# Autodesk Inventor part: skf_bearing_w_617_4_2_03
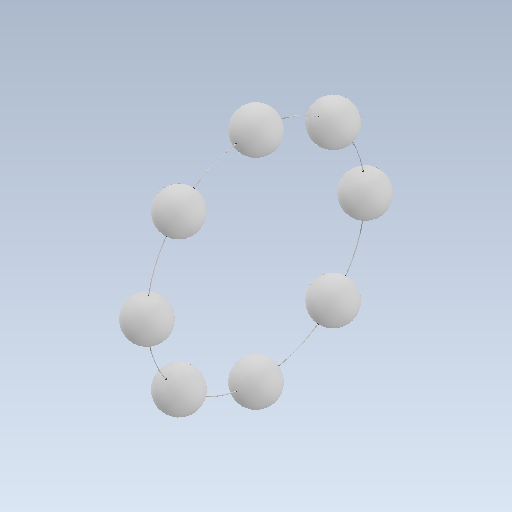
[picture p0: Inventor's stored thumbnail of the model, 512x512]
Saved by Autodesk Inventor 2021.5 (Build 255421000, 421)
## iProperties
Created: 2023-11
Part Number: skf_bearing_w_617_4_2_03
Checked By: TraceParts S.A.
Material: Generic
Catalog Web Link: www.traceparts.com
Document SubType Name: Modeling
Designer: TraceParts
Density: 1 g/cm^3
Appearance: Default
Company: TraceParts S.A.
Author: TraceParts
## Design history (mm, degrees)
feature "skf_bearing_w_617_4_2_03.ipt"
body "Solid1"
